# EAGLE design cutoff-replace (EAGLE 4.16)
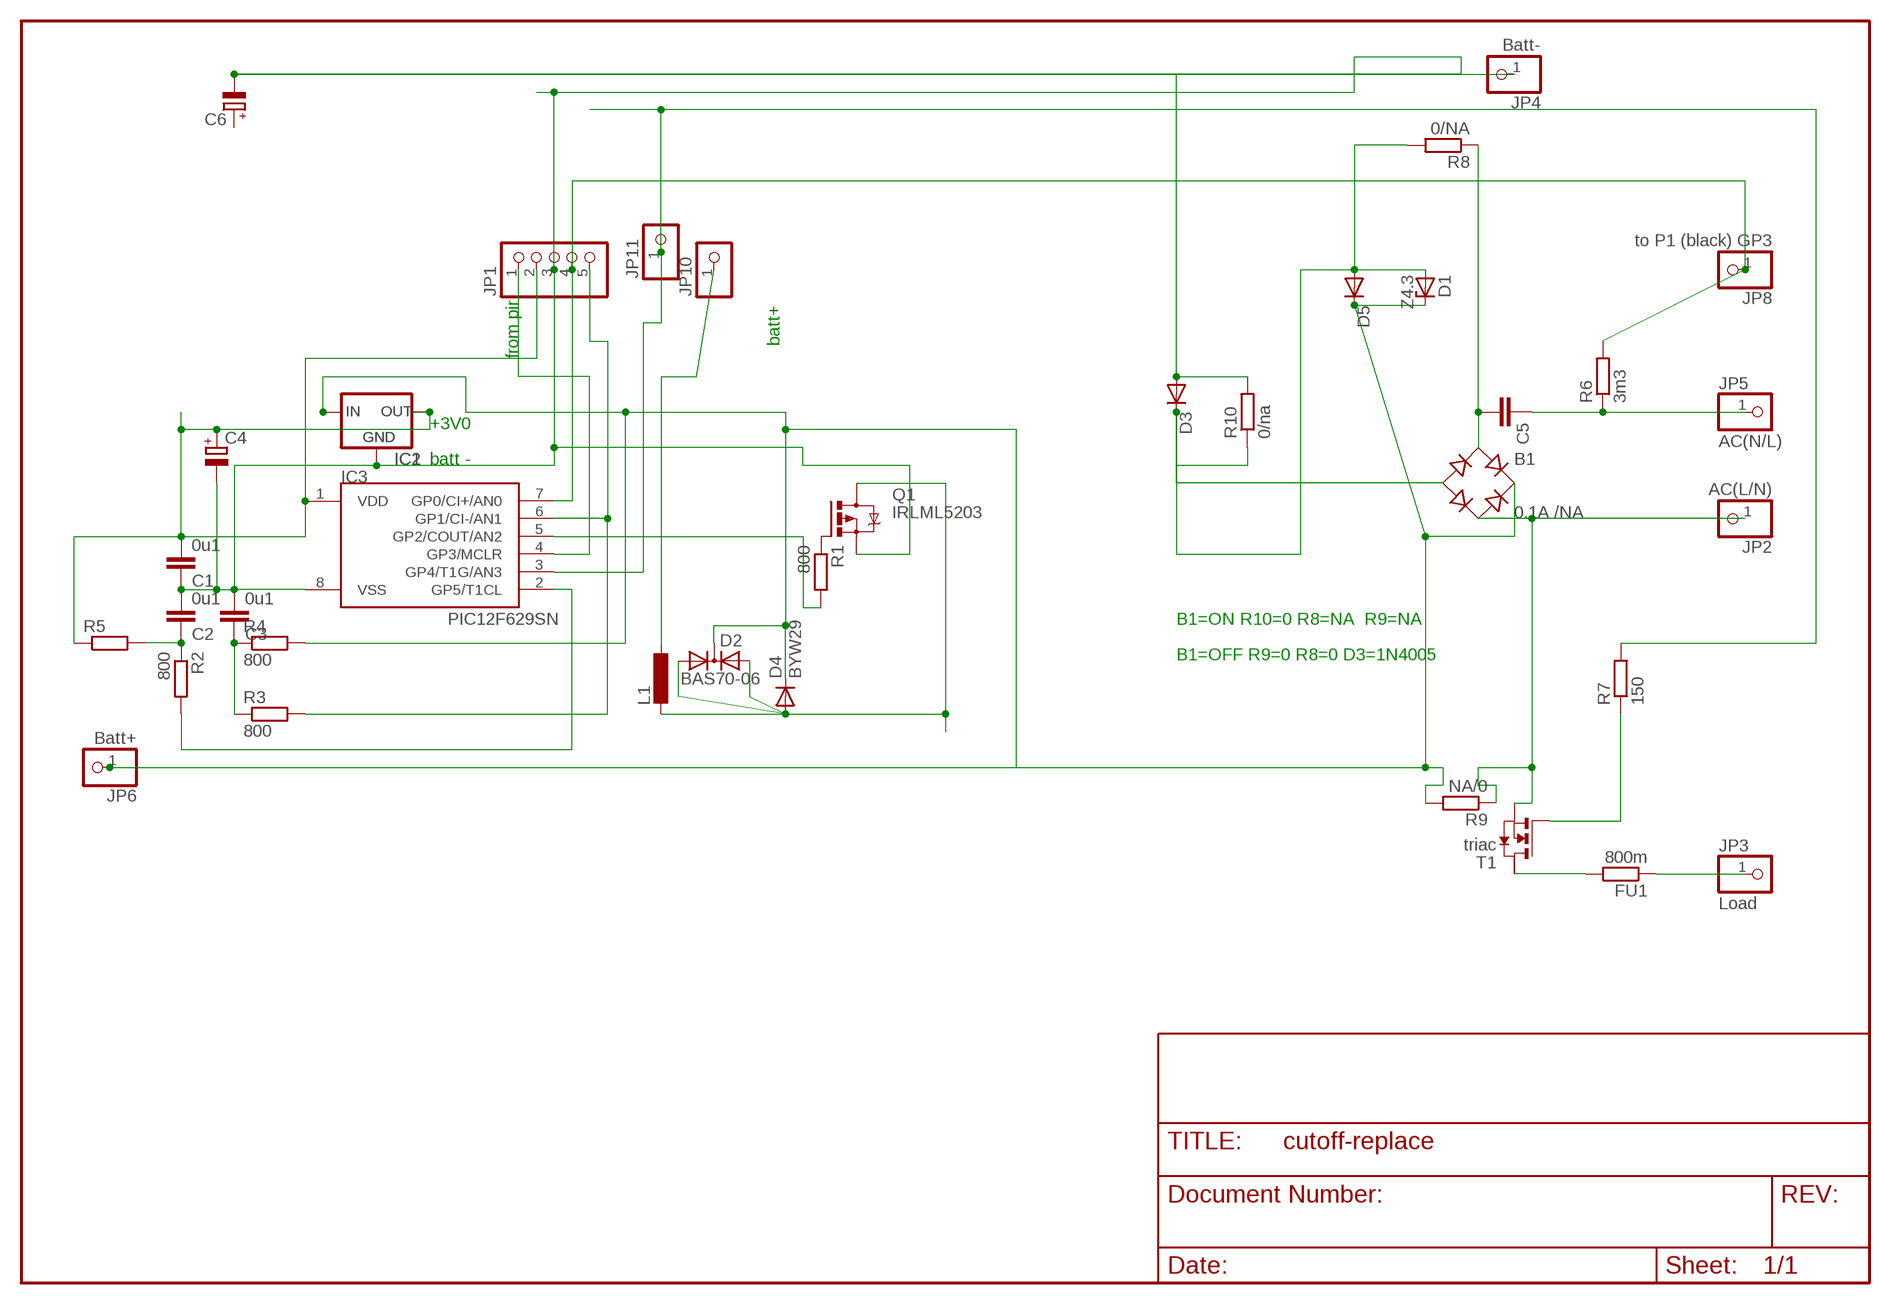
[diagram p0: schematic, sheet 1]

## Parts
B1  0.1A /NA  RECTIFIER-B40S  [B40S]
C1  0u1  C-EUC1206  [C1206]
C2  0u1  C-EUC1206  [C1206]
C3  0u1  C-EUC1206  [C1206]
C4  CPOL-EUE2.5-6  [E2,5-6]
C5  C-EU050-025X075  [C050-025X075]
C6  CPOL-EUE2,5-6E  [E2,5-6E]
D1  Z4.3  ZENER-DIODESOT23  [SOT23]
D2  BAS70-06  [SOT23]
D3  DIODE-MELF-MLL41  [MELF-MLL41]
D4  BYW29  [DO220S]
D5  DIODE-MINIMELF  [MINIMELF]
FU1  800m  R-EU_0204/5  [0204/5]
IC1  XC63FPP  [SOT89R]
IC2  XC63FPT  [TO92]
IC3  PIC12F629SN  [SO-08]
JP1  PINHD-1X5  [1X05]
JP2  AC(L/N)  PINHD-1X1  [1X01]
JP3  Load  PINHD-1X1  [1X01]
JP4  Batt-  PINHD-1X1  [1X01]
JP5  AC(N/L)  PINHD-1X1  [1X01]
JP6  Batt+  PINHD-1X1  [1X01]
JP8  to P1 (black) GP3  PINHD-1X1  [1X01]
JP10  PINHD-1X1  [1X01]
JP11  PINHD-1X1  [1X01]
L1  L-EU0207/7  [0207/7]
Q1  IRLML5203  [MICRO3]
R1  800  R-EU_R1206  [R1206]
R2  800  R-EU_R1206  [R1206]
R3  800  R-EU_R1206  [R1206]
R4  800  R-EU_R1206  [R1206]
R5  R-EU_0411/3V  [0411V]
R6  3m3  R-EU_R1206  [R1206]
R7  150  R-EU_R1206  [R1206]
R8  0/NA  R-EU_R1206  [R1206]
R9  NA/0  R-EU_R1206  [R1206]
R10  0/na  R-EU_R1206  [R1206]
T1  triac  NMOSSOT223  [SOT223]

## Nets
N$1: C1.1 C2.2 C3.2 C4.- C6.- D3.A IC1.1(GND) IC2.1(GND) IC3.8(VSS) JP1.3 JP4.1 Q1.2(S) R10.2
N$2: IC3.2(GP5/T1CL) R2.2
N$3: B1.+ D1.3(C) D2.3(C) D4.C D5.C IC1.2(IN) IC2.2(IN) JP6.1 R4.2 R9.2
N$4: IC3.3(GP4/T1G/AN3) JP11.1 R7.2
N$5: D2.1(A1) D2.2(A2) D4.A L1.2 Q1.3(D)
N$6: C1.2 C4.+ IC1.3(OUT) IC2.3(OUT) IC3.1(VDD) JP1.2 R5.1
N$7: C3.1 R3.1 R4.1
N$8: IC3.6(GP1/CI-/AN1) JP1.5 R3.2
N$9: IC3.4(GP3/MCLR) JP1.1
N$11: C2.1 R2.1 R5.2
N$12: Q1.1(G) R1.1
N$14: IC3.7(GP0/CI+/AN0) JP1.4 JP8.1 R6.2
N$16: IC3.5(GP2/COUT/AN2) R1.2
N$17: JP10.1 L1.1
N$18: FU1.1 JP3.1
N$19: FU1.2 T1.2(D)
N$21: R7.1 T1.1(G)
N$23: B1.AC2 JP2.1 R9.1 T1.3(S)
N$25: B1.- D1.1(A) D3.C D5.A R8.2 R10.1
N$26: B1.AC1 C5.2 R8.1
N$37: C5.1 JP5.1 R6.1
Unconnected: C6.+ T1.4(D2)

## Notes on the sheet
- batt+
- from pir
- +3V0
- batt -
- B1=ON R10=0 R8=NA  R9=NA
- B1=OFF R9=0 R8=0 D3=1N4005

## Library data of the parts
B1 = rectifier:RECTIFIER-: Rectifier
C1-C3 C5 = rcl:C-EU: CAPACITOR, European symbol
C4 C6 = rcl(2):CPOL-EU: POLARIZED CAPACITOR, European symbol
D1 = diode-1:ZENER-DIODE: Z-Diode
D2 = diode-1:BAS70-06: Silicon Schottky Diodes General-purpose diode for high-speed switching
D3 D5 = diode-1:DIODE-: DIODE
D4 = diode:BYW29: DIODE
FU1 R1-R10 = rcl:R-EU_: RESISTOR, European symbol
IC1 IC2 = v-reg:XC63FP: Positiv Voltage Regulators www.torex.co.jp/english/product/pro02/pdf/0201_xc62fp.pdf
IC3 = microchip-3:PIC12F6*: uPC nW 1k Program Flash memory 2x Timer Comparator 10b A/D converter/ 4xIN
JP1 = pinhead(2):PINHD-1X5: PIN HEADER
JP2-JP6 JP8 = pinhead:PINHD-1X1: PIN HEADER
JP10 JP11 = pinhead(2):PINHD-1X1: PIN HEADER
L1 = rcl:L-EU: INDUCTOR, European symbol
Q1 = transistor-power:IRLML5203: HEXFET P-Channel Power MOSFET
T1 = zetex:NMOSSOT223: MOS FET

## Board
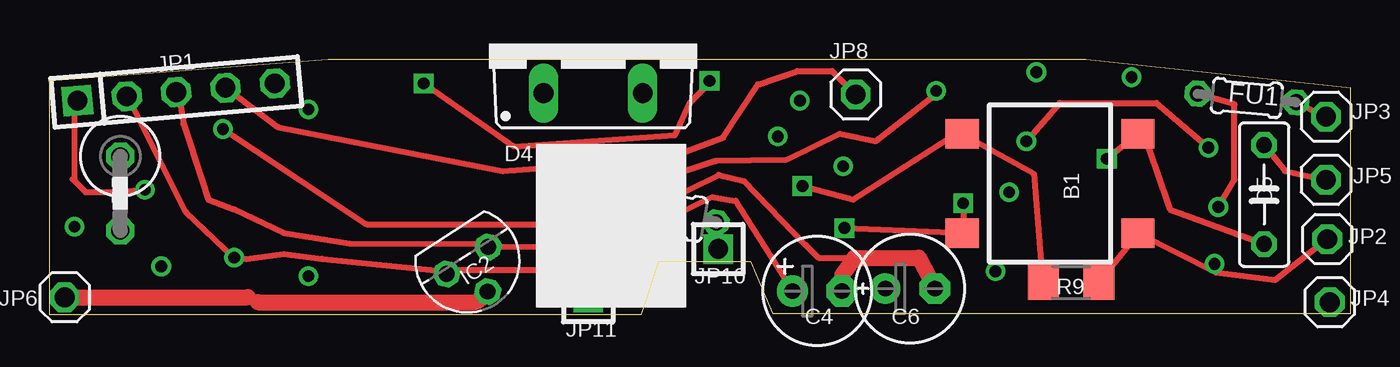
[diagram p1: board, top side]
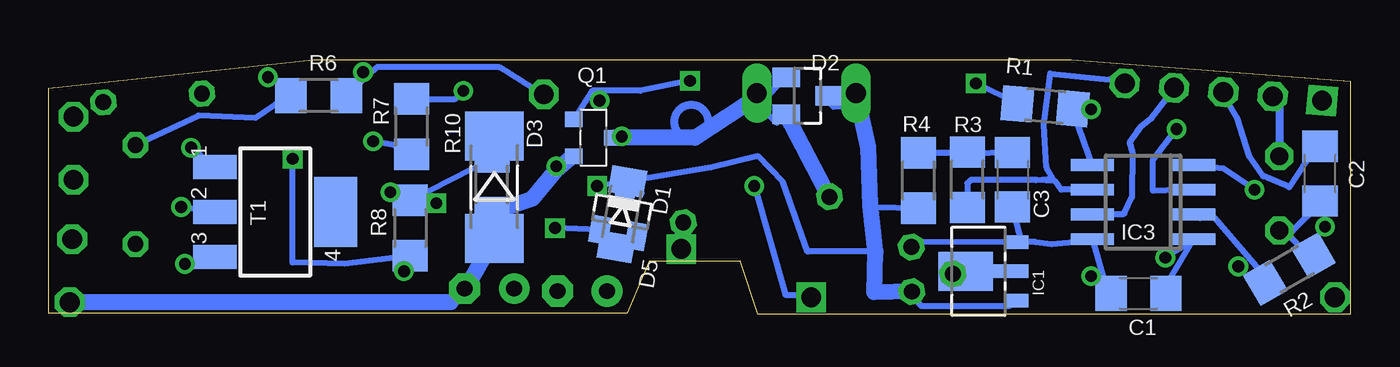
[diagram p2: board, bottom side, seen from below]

Size 66.76 x 13.08 mm. Coordinates in mm from the lower left corner, seen from the top.
Outline: 0,0 30.38,0 31.27,2.73 35.97,2.73 37.11,0.06 66.76,0.06 66.76,11.61 53.18,13.07 52.41,13.08 18,13.07 14.31,13.08 0,11.99 0,0
Copper layers (1*16): Top 0.035mm / dielectric 1.5mm / Bottom 0.035mm
Design rules "default": minimum track width 10mil, minimum drill 2mil, track to track 8mil, track to pad 8mil, pad to pad 8mil, via to via 8mil, smd to smd 8mil, copper to edge 1mil, drill to drill 8mil, minimum pad ring 10mil, minimum via ring 8mil, stop-mask expansion 4mil, vias tented up to drill 0mil, thermal gap 10mil

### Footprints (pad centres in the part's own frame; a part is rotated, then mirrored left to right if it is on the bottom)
B40S = smd 1.5 x 1.7: + -2.55,-4.5; - 2.55,-4.5; AC1 -2.55,4.5; AC2 2.55,4.5
C1206 = smd 1.6 x 1.8: 1 -1.4,0; 2 1.4,0
E2,5-6 = drill 0.813 pad 1.6 round: + -1.27,0 | drill 0.813 pad 1.6 octagon: - 1.27,0
C050-025X075 = drill 0.813 octagon: 1 -2.54,0; 2 2.54,0
E2,5-6E = drill 0.813 pad 1.575 round: + -1.27,0 | drill 0.813 pad 1.575 octagon: - 1.27,0
SOT23 = smd 1 x 1.4: 1 -0.95,-1.1; 2 0.95,-1.1; 3 0,1.1
MELF-MLL41 = smd 2.5 x 3: A 2.625,0; C -2.625,0
DO220S = drill 1.016 long: A 2.54,-2.54; C -2.54,-2.54
MINIMELF = smd 1.4 x 1.8: A 1.7,0; C -1.7,0
0204/5 = drill 0.813 octagon: 1 -2.54,0; 2 2.54,0
SOT89R = smd 0.7 x 1.1: 1 1.5,-1.75; 2 -1.5,-1.75 | smd 0.7 x 1.8: 3 0,-1.4 | smd 2 x 2.8: 4 0,0.9
TO92 = drill 0.813 octagon: 1 -1.27,0; 2 0,1.905; 3 1.27,0
SO-08 = smd 0.6 x 2.2: 1 -1.905,-2.6; 2 -0.635,-2.6; 3 0.635,-2.6; 4 1.905,-2.6; 5 1.905,2.6; 6 0.635,2.6; 7 -0.635,2.6; 8 -1.905,2.6
1X05 = drill 1.016 square: 1 -5.08,0 | drill 1.016 octagon: 2 -2.54,0; 3 0,0; 4 2.54,0; 5 5.08,0
1X01 = drill 1.016 octagon: 1 0,0
1X01' = drill 1.016 square: 1 0,0
0207/7 = drill 0.813 octagon: 1 -3.81,0; 2 3.81,0
MICRO3 = smd 0.8 x 0.9: 1 -0.95,-1; 2 0.95,-1; 3 0,1
R1206 = smd 1.6 x 1.803: 1 -1.422,0; 2 1.422,0
0411V = drill 0.914 octagon: 1 -2.54,0; 2 1.27,0
SOT223 = smd 1.219 x 2.235: 1 -2.311,-3.099; 2 0,-3.099; 3 2.311,-3.099 | smd 3.6 x 2.2: 4 0,3.099

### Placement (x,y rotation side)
B1  51.33,6.73 270 top
C1  10.87,1.09 0 bottom
C2  1.55,7.23 90 bottom
C3  17.32,6.92 270 bottom
C4  39.4,1.2 0 top
C5  62.32,6.15 270 top
C6  44.16,1.33 0 top
D1  37.36,5.27 350 bottom
D2  27.84,11.23 270 bottom
D3  43.9,6.54 270 bottom
D4  27.9,13.9 0 top
D5  37.36,5.15 260 bottom
FU1  61.44,11.12 175 top
IC1  18.82,2.22 90 bottom
IC2  21.45,2.77 213 top
IC3  10.63,5.77 90 bottom
JP1  6.51,11.42 5 top
JP2  65.56,3.87 0 top
JP3  65.49,10.15 0 top
JP4  65.68,0.63 0 top
JP5  65.49,6.92 0 top
JP6  0.79,0.88 0 top
JP8  41.36,11.3 0 top
JP10  [1X01']  34.32,3.36 0 top
JP11  [1X01']  27.65,0.88 0 top
L1  30.46,5.38 170 top
Q1  38.82,9.08 270 bottom
R1  15.65,10.7 355 bottom
R2  3.13,2.33 210 bottom
R3  19.65,6.92 270 bottom
R4  22.15,6.88 270 bottom
R5  3.65,5.58 270 top
R6  52.92,11.23 0 bottom
R7  48.16,9.65 90 bottom
R8  48.22,4.44 90 bottom
R9  52.41,1.65 180 top
R10  44.03,6.66 270 bottom
T1  55.14,5.27 270 bottom

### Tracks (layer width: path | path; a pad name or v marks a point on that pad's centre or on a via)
N$1
  Top 0.305: 22.52,3.41 22.69,3.23 | 22.52,3.41 IC2.1 | 22.31,3.61 22.52,3.41 | 22.31,3.61 22.12,3.81 | 22.31,3.61 IC2.1 | 41.3,2.92 39.46,2.92 38.82,3.55 35.65,6.85 34.35,7.17 26.89,3.49 IC2.1 | 22.31,3.61 15.4,3.64 12.03,4.19 9.49,5.39 8.15,5.9 6.89,9.76 6.63,11.3 JP1.3
  Top 0.813: C6.- 44.6,2.92 41.3,2.92 40.67,2.03 C4.-
  Bottom 0.305: C2.2 2.25,7.87 3.14,6.54 4.47,7.11 5.17,8.12 5.8,10.09 6.36,11.02 6.5,11.23 6.5,11.36 6.56,11.42 | C3.2 16.88,3.78 17.04,3.61 17.07,3.64 IC1.1 16.13,3.72 | 16.13,3.72 15.33,3.61 13.23,3.81 IC3.8 12.55,1.41 C1.1 | 46.13,0.63 C6.- 45.36,1.33 | 43.08,5.58 R10.2 44.03,4.06 D3.A | IC2.1 22.31,3.74 16.13,3.72 | 6.56,11.42 6.57,11.42 | 6.56,11.42 JP1.3
  Bottom 0.813: 46.13,0.63 JP4.1 | Q1.2 39.9,8.12 40.73,7.42 41.94,5.96 43.08,5.58 | 45.36,1.33 D3.A
N$2
  Bottom 0.305: R2.2 4.64,2.26 6.95,4.95 7.71,4.95 7.96,5.2 IC3.2
N$3  (via drill 0.6)
  Top 0.305: 10.19,0.88 10.69,0.63 | 22.69,1.2 IC2.2 | v38.63,6.6 41.24,5.9 46.7,9.39 B1.+ 50.51,7.23 50.95,1.77 R9.2
  Top 0.813: JP6.1 10.19,0.88 | 10.69,0.63 21.87,0.63 22.69,1.2
  Bottom 0.305: IC2.2 22.49,0.93 22,0.44 17.49,0.44 17.21,0.72 IC1.2 | D2.3 26.63,10.79 26.51,10.66 25.36,10.66 D4.C | 24.62,5.58 24.47,5.52 R4.2 | D5.C 32.79,7.55 30.38,8.12 29.11,6.79 27.84,3.23 24.35,3.23 | D5.C v38.63,6.6 | D5.C 36.35,6.22 D1.3
  Bottom 0.813: IC2.2 24.41,1.14 24.35,3.23 24.62,5.58 24.73,8.57 25.3,11.23 D4.C
N$4  (via drill 0.6)
  Top 0.305: v8.92,9.52 16.28,4.63 27.2,4.63 28.98,5.84 v30.57,6.6 30.57,6.66 34.19,7.87 37.81,7.93 40.54,9.27 42.38,8.88 45.21,11.07 v45.49,11.49
  Bottom 0.305: IC3.3 10.12,6.34 10.12,7.93 v8.92,9.52 | v30.57,6.6 28.98,1.01 27.52,1.01 JP11.1 | R7.2 45.91,11.07 v45.49,11.49
N$5
  Bottom 0.305: D4.A 30.32,10.73 29.43,9.84 D2.2 | D4.A 30.25,10.85 D2.1 | D4.A 30.25,11.3
  Bottom 0.813: L1.2 26.95,6.47 D2.2 | Q1.3 33.62,9.08 30.25,11.3
N$6  (via drill 0.6)
  Top 0.305: 4.03,11.2 4.03,11.23 | 4.03,11.2 JP1.2 | 4.03,11.2 4.03,10.79 4.28,10.66 7.01,5.27 v9.49,2.92 10.12,2.85 12.03,3.1 14,2.86 20.35,2.22 IC2.3 20.28,2.28 25.87,2.28 26.25,2.66 27.11,2.66 34,6.03 35.2,5.84 C4.+
  Bottom 0.305: IC3.1 8.28,3.87 | v9.49,2.92 9.17,3.11 8.15,3.74 IC3.1 | C1.2 9.74,0.97 IC3.1 | IC2.3 20.22,2.15 IC1.3
  Bottom 0.406: JP1.2 3.98,11.06 3.64,10.73 R5.1
N$7
  Bottom 0.305: 19.67,8.34 19.71,8.38 | 19.67,8.34 R3.1 19.74,8.34 19.77,8.38 19.85,8.3 R4.1 | C3.1 19.59,8.25 19.67,8.34
N$8
  Top 0.305: JP1.5 11.46,12
  Bottom 0.305: IC3.6 14.83,6.41 15.14,6.85 16.15,6.92 | 16.15,6.92 16.09,6.92 15.27,6.98 15.58,7.55 15.73,9.75 15.39,12.38 12.34,12.07 JP1.5 | 16.15,6.92 19.46,6.92 19.65,6.73 R3.2
N$9  (via drill 0.6)
  Top 0.305: v4.91,6.41 3.45,6.28 1.87,6.28 1.2,6.95 1.3,6.95 1.3,10.98 JP1.1
  Bottom 0.305: v4.91,6.41 6.52,7.5 7.07,7.55 7.9,7.55 IC3.4
N$11
  Bottom 0.305: R2.1 2.12,3.04 3.45,4.38 3.52,4.31 R5.2 2.95,4.31 1.55,5.71 C2.1
N$12  (via drill 0.6)
  Top 0.305: v19.2,11.87 23.84,8.63 32.09,9.2 32.86,10.85 33.87,11.87 v33.87,12
  Bottom 0.305: R1.1 v19.2,11.87 | v33.87,12 36.41,11.49 38.89,11.49 Q1.1
N$14
  Top 0.305: JP8.1 40.16,12.5 38.38,12.5 36.35,11.81 34.57,9.08 32.64,8.38 24.98,7.49 23.27,7.36 11.73,9.63 JP1.4
  Bottom 0.305: IC3.7 11.64,5.14 11.58,5.2 11.2,6.03 11.18,8.34 11.33,8.82 10.75,9.64 | 10.75,9.64 10.95,9.39 | 10.75,9.64 10.19,10.08 8.96,11.67 JP1.4 | R6.2 49.94,12.69 43.65,12.69 41.94,11.61 JP8.1
N$15  (via drill 0.6)
  other vias: 13.3,1.96
N$16
  Bottom 0.305: R1.2 14.38,10.92 IC3.5
N$17
  Bottom 0.305: JP10.1 34.25,3.61
  Bottom 0.813: 34.25,3.61 L1.1
N$18
  Top 0.305: FU1.1 64.67,10.54 JP3.1
N$19  (via drill 0.6)
  Top 0.305: v59.97,5.52 60.8,6.92 60.8,10.79 FU1.2
  Bottom 0.305: T1.2 v59.97,5.52
N$20  (via drill 0.6)
  other vias: 13.3,10.54
N$21  (via drill 0.6)
  Top 0.305: v59.46,8.57 56.79,10.85 51.84,10.85 v50.13,8.88
  Bottom 0.305: v59.46,8.57 T1.1 | R7.1 49.05,8.69 v50.13,8.88
N$22  (via drill 0.6)
  other vias: 5.74,2.47
N$23  (via drill 0.6)
  Top 0.305: JP2.1 62.89,1.77 59.84,2.15 | 59.84,2.15 B1.AC2 55.91,4.19 R9.1 | 59.84,2.15 59.72,2.28 v59.78,2.6
  Bottom 0.305: T1.3 58.06,3.11 v59.78,2.6
N$24  (via drill 0.6)
  other vias: 1.3,4.5
N$25  (via drill 0.6)
  Top 0.305: 46.95,4.19 B1.- | v40.79,4.44 46.95,4.19 | 46.95,4.19 v46.89,5.71
  Bottom 0.305: D5.A 38.38,3.61 D1.1 v40.79,4.44 | v46.89,5.71 48.03,5.77 R8.2 44.03,8 R10.1 43.97,9.14 D3.C
N$26  (via drill 0.6)
  Top 0.305: v54.25,8 B1.AC1 56.1,9.39 57.49,5.39 C5.2
  Bottom 0.305: R8.1 51.59,2.6 54.25,2.66 v54.25,8
N$27  (via drill 0.6)
  other vias: 50.63,12.44
N$28  (via drill 0.6)
  other vias: 55.52,12.19
N$29  (via drill 0.6)
  other vias: 48.54,2.22
N$30  (via drill 0.6)
  other vias: 37.36,9.14
N$31  (via drill 0.6)
  other vias: 38.51,10.98
N$32  (via drill 0.6)
  other vias: 40.73,7.62
N$33  (via drill 0.6)
  other vias: 49.24,6.28
N$37
  Top 0.305: C5.1 63.4,7.36 JP5.1
  Bottom 0.305: C5.1 59.08,10.22 56.16,10.09 54.19,11.42 R6.1
(copper drawn outside any net)
  shapes: Bottom circle x1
